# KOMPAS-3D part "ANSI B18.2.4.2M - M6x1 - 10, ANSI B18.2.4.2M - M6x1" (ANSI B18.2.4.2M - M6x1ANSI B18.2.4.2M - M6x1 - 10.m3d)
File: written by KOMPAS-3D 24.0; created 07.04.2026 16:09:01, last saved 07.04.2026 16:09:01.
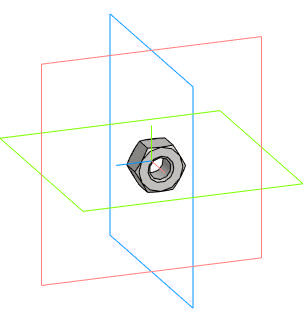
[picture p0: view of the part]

Document properties: Автор: Main; Полное имя файла: D:\DN.ru Аутсерс\Стекло смотровое DN.ru\Исходники\Стекло смотровое DN.ru SG2-34G-F тип В ГОСТ 21836-2021 Ду32 Ру40, углеродистая сталь, фланцевое\ANSI B18.2.4.2M - M6x1ANSI B18.2.4.2M - M6x1 - 10.m3d

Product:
- Body: Solid1  | qty 1
- Part/product: ANSI B18.2.4.2M - M6x1 - 10  | designation ANSI B18.2.4.2M - M6x1
    Комментарий: Типы метрических   шестигранных гаек   2
    additional columns: Сталь, мягкая

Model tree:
1. Solid1  (labels: Solid1)

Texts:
  ANSI B18.2.4.2M - M6x1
